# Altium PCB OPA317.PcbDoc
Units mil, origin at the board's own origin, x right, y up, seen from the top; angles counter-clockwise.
Board outline 2110 x 1700 mil, 2 copper layers (Top Layer, Bottom Layer), stack 62 mil thick; 30 components, 25 nets, 78 pads, 25 vias.
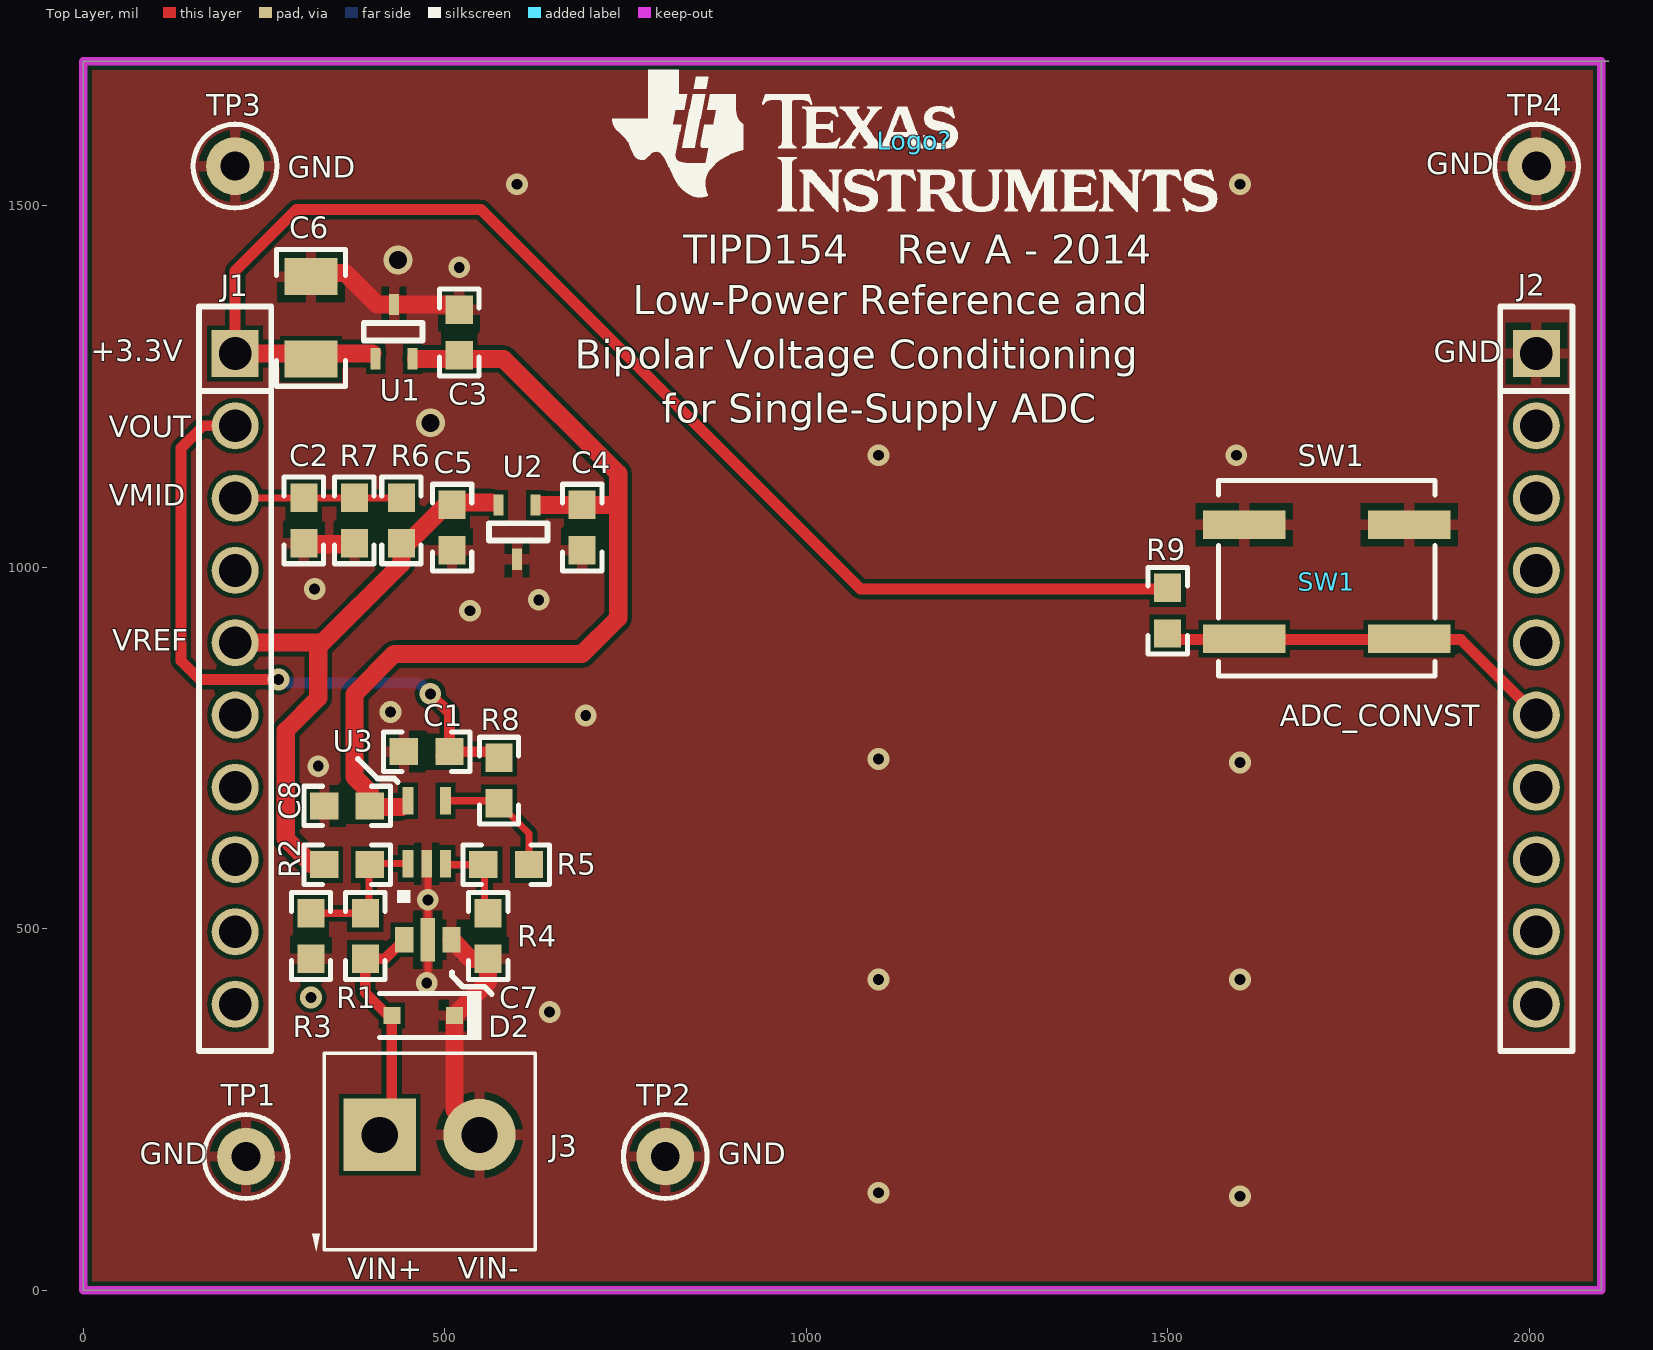
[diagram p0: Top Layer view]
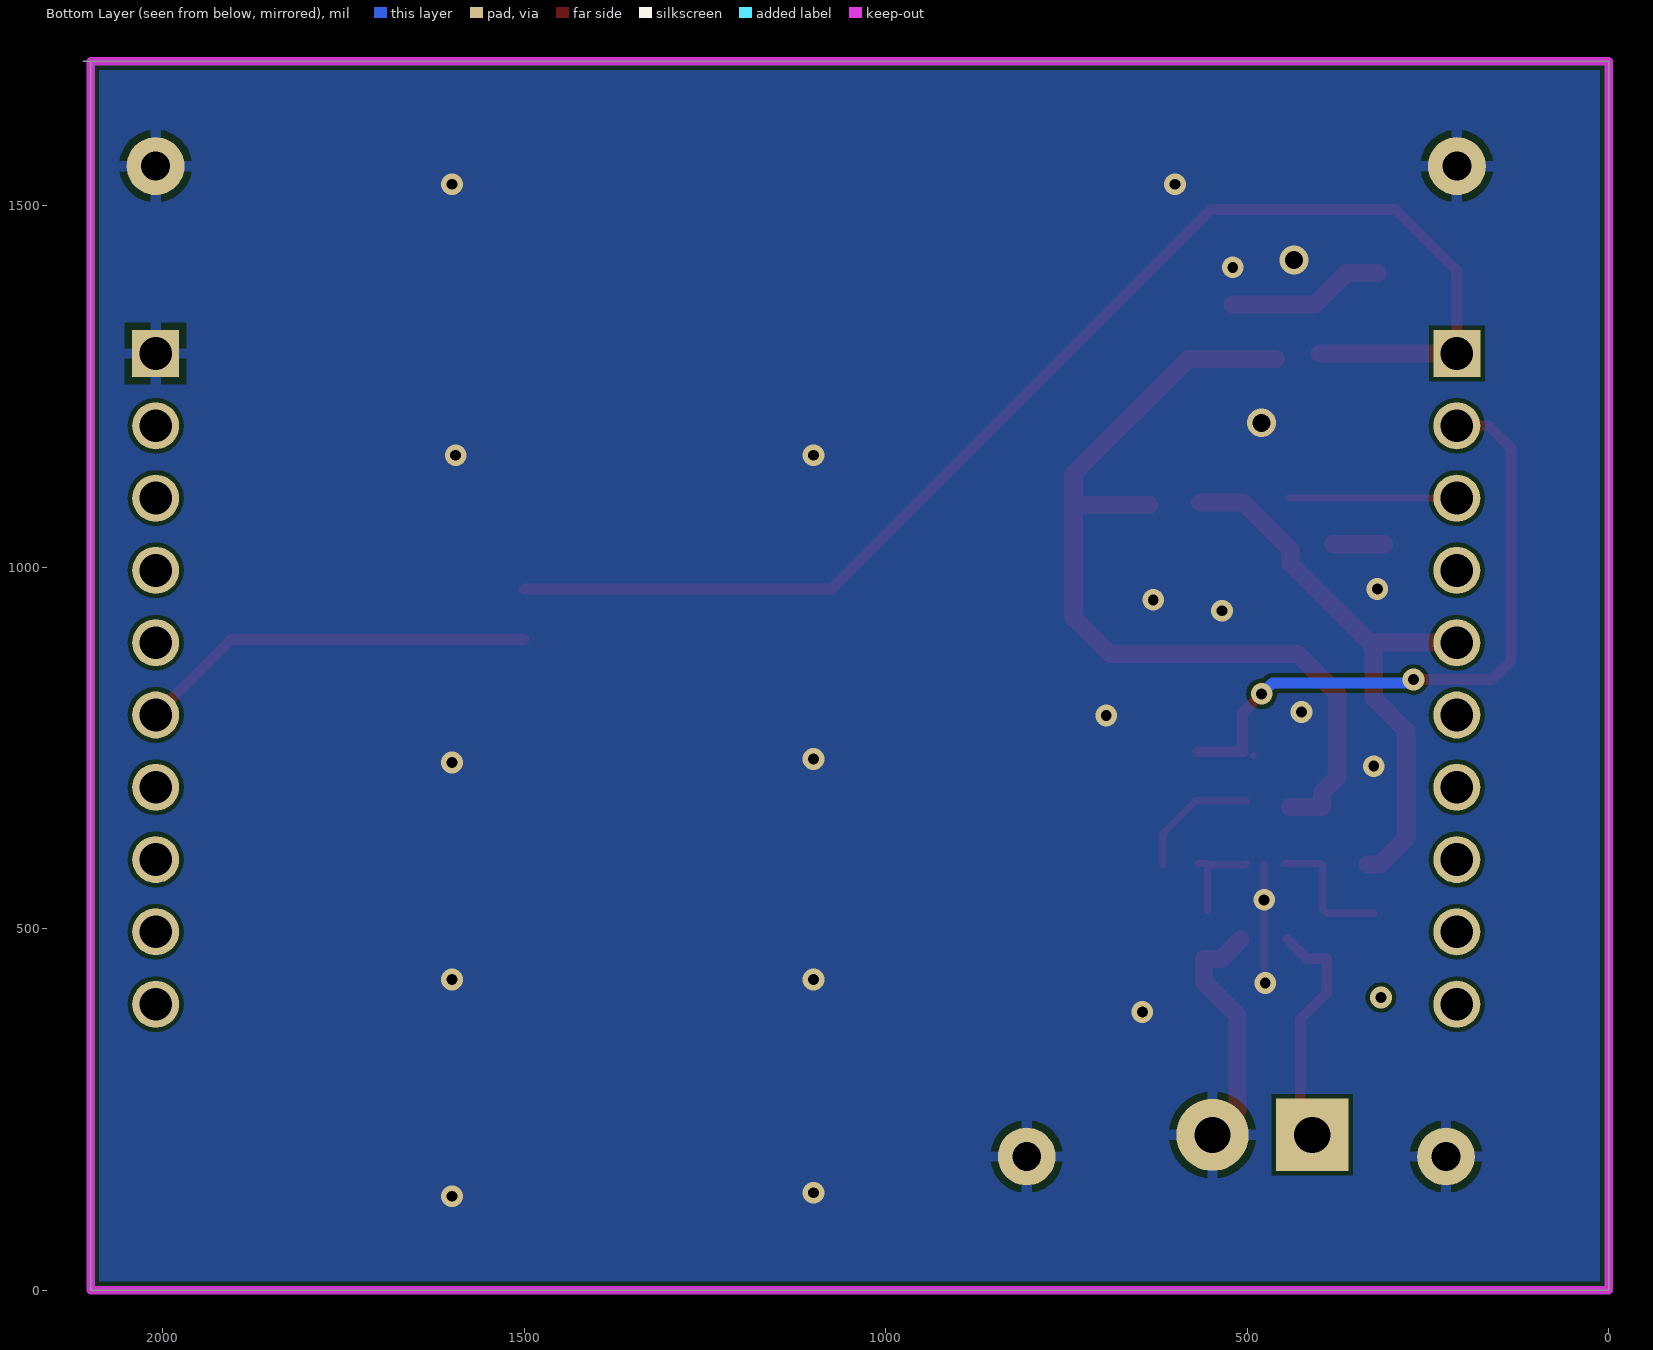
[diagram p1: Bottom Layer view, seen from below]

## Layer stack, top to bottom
Top Layer: signal copper 1.4
Dielectric: core 59.2, FR-4, Dk 4.8
Bottom Layer: signal copper 1.4

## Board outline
2110,1700 0,1700 0,0 2100,0 2100,1700

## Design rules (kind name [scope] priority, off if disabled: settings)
AcuteAngle [All] p1: minimum=4.50000000000000E+0001 checktracksonly=FALSE
AssemblyTestPointUsage [All] p1: valid=2
Clearance [All] p1: gap=6
DiffPairsRouting [All] p1: maxlimit=10 minlimit=10 mostfreqgap=10 maxuncoupledlength=1000
FanoutControl Fanout_LCC [IsLCC] p1: bgadir=Out bgaviamode=Centered fanoutstyle=Auto fanoutdirection=Alternating viagrid=1 // Fanout_LCC (Default Rule)
FanoutControl Fanout_BGA [IsBGA] p2: bgadir=Out bgaviamode=Centered fanoutstyle=Auto fanoutdirection=Alternating viagrid=1 // Fanout_BGA (Default Rule)
FanoutControl Fanout_Default [All] p4: bgadir=Out bgaviamode=Centered fanoutstyle=Auto fanoutdirection=Alternating viagrid=1 // Fanout_Default (Default Rule)
FanoutControl Fanout_Small [(CompPinCount < 5)] p5: bgadir=Out bgaviamode=Centered fanoutstyle=Auto fanoutdirection=OutThenIn viagrid=1 // Fanout_Small (Default Rule)
HoleToHoleClearance [All] p1: gap=0 allowstackedmicrovias=TRUE
MinimumSolderMaskSliver [All] p1: minsoldermaskwidth=0
PolygonConnect PolygonConnect_1 [(InComponentClass('All Components'))] p1: connectstyle=Relief reliefconductorwidth=15 reliefentries=4 polygonreliefangle="90 Angle" airgapwidth=10
PolygonConnect [All] p2: connectstyle=Direct reliefconductorwidth=20 reliefentries=4 polygonreliefangle="90 Angle" airgapwidth=10
RoutingVias [All] p1: holewidth=15 width=30 viastyle="Through Hole" minholewidth=15 minwidth=30 maxholewidth=28 maxwidth=50
SilkToSilkClearance [All] p1 off: silktosilkclearance=10
SilkscreenOverComponentPads [All] p1 off: minsilkscreentomaskgap=10
SolderMaskExpansion [All] p1: expansion=4
Width [All] p1: maxlimit=25 minlimit=10 preferedwidth=10
18 further rules are at their usual default settings.

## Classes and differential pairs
component class Logo: Logo?

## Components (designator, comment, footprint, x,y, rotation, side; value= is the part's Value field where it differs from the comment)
C1 "GRM188R71C154KA01D" 0603 475,745 r180 top
C2 "GRM188R60J476M" 0603 305,1065 r270 top
C3 "C1608X7R1C105K" 0603 520,1325 r90 top
C4 "C1608X7R1C105K" 0603 690,1055 r270 top
C5 "C1608X7R1C105K" 0603 510,1055 r270 top
C6 "C3216X7R1C106M" 1206 315,1345 r90 top
C7 "1000pF X2Y" X2Y_0603 476.59,485 r180 top
C8 "GRM188R71H104KA93D" 0603 365,670 r180 top
D2 "CDSOD323-T15SC" sod-323 470,380 r180 top
J1 "SSW-110-23-F-S" CONN_SSW-110-23-F-S 209.99,1295.82 r90 top
J2 "SSW-110-23-F-S" CONN_SSW-110-23-F-S 2009.99,1295.82 r90 top
J3 "ED555/2DS" TERM_BLK_ED555-2DS 410,215 r0 top
Logo? "Texas Instruments" TI_Stacked_Overlay_Small 1150,1590 r0 top
R1 "RG1608P-104-B-T5" 0603 390,490 r90 top
R2 "RG1608P-203-B-T5" 0603 365,588.7 r180 top
R3 "RG1608P-203-B-T5" 0603 315,490 r90 top
R4 "RG1608P-104-B-T5" 0603 560,490 r90 top
R5 "RG1608P-103-B-T5" 0603 585,588.7 r0 top
R6 "RG1608P-473-B-T5" 0603 440,1065 r270 top
R7 "RG1608P-473-B-T5" 0603 375,1065 r90 top
R8 "RT0603BRD071KL" 0603 575,705 r90 top
R9 "RG1608P-104-B-T5" 0603 1500,940 r90 top
SW1 "KSC222J LFS" "KSC222J LFS" 1720,980 r180 top
TP1 "5001" Keystone5001 225,185 r90 top
TP2 "5001" Keystone5001 805,185 r90 top
TP3 "5001" Keystone5001 210,1555 r90 top
TP4 "5001" Keystone5001 2010,1555 r90 top
U1 "REF3330AIDCKT" SC70 680,1525 r0 top
U2 "REF3312AIDCKR" SC70 350,850 r180 top
U3 "OPA317IDCKR" SC-70-5 475,633.7 r0 top

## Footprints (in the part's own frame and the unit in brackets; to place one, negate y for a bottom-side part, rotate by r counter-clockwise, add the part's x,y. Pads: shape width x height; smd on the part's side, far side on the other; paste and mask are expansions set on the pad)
0603 [mm] "0603 from SM-752 data"
  rect 1x0.95 smd: 1(-0.8,0) 2(0.8,0)
  silkscreen extent -1.52,-0.69 1.52,0.69, body extent -0.87,-0.47 0.87,0.47, height 0.85
1206 [mm] "1206 from SM-752 data"
  rect 1.3x1.85 smd: 1(-1.45,0) 2(1.45,0)
  silkscreen extent -2.4,-1.21 2.4,1.21, body extent -1.7,-0.9 1.7,0.9, height 1.35
CONN_SSW-110-23-F-S [mm] "SAMTEC"
  rect 1.65x1.65 hole 1.15: 1(0,0)
  round 1.65 hole 1.15: 2(-2.54,0) 3(-5.08,0) 4(-7.62,0) 5(-10.16,0) 6(-12.7,0) 7(-15.24,0) 8(-17.78,0) 9(-20.32,0) 10(-22.86,0)
  silkscreen extent -24.51,-1.27 1.65,1.27, body extent -24.43,-1.27 1.57,1.27, height 8.59
Keystone5001 [mil] "For Keystone 500x miniature loop terminals"
  round 80 hole 40: 1(0,0)
  silkscreen extent -58,-58 58,58, body extent -49,-49 49,49, height 182
"KSC222J LFS" [mm]
  rect 2.9x1 smd mask+0: 1(-2.9,2) 2(-2.9,-2) 3(2.9,-2) 4(2.9,2)
  silkscreen extent -3.81,-3.56 3.81,3.3, body extent -3.3,-3.05 3.3,3.05, height 3.51
SC70 [mm]
  rect 0.35x0.75 smd: 1(-7,-6) 2(-5.7,-6) 3(-6.35,-4.1)
  silkscreen extent -7.42,-5.36 -5.36,-4.75
SC-70-5 [mil]
  rect 15x38 smd: 1(-25.9,-43.4) 2(0.1,-43.4) 3(26.1,-43.4) 4(26.1,43.6) 5(-25.9,43.6)
  silkscreen extent -41,-97 -23,-80
sod-323 [mm] "NXP recommended land pattern"
  rect 0.6x0.6 smd paste-0.05: 1(-1.1,0) 2(1.1,0)
  silkscreen extent -2.06,-0.86 1.53,0.86, body extent -1.3,-0.67 1.3,0.68, height 1.1
TERM_BLK_ED555-2DS [mil]
  rect 100x100 hole 50: 1(0,0)
  round 100 hole 50: 2(138,0)
  silkscreen extent -93,-161 215,113, body extent -69,-150 207,106, height 323
TI_Stacked_Overlay_Small [mil]
  silkscreen extent -418,-98 418,98
X2Y_0603 [mm] "JOHANSON DIELECTRICS"
  rect 0.64x0.89 smd: 1(-0.83,0) 2(0.83,0)
  rect 0.51x1.52 smd: 3(0,0)
  body extent -0.88,-0.51 0.88,0.51, height 0.66

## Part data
C1: "CAP, CERM, 0.15uF, 16V, +/-10%, X7R, 0603"
C2: "CAP, CERM, 47uF, 6.3V, +/-20%, X5R, 0603"
C3 C4 C5: "CAP, CERM, 1uF, 16V, +/-10%, X7R, 0603"
C6: "CAP, CERM, 10uF, 16V, +/-20%, X7R, 1206"
C7: library part "X2Y Capacitor", "CAP CER 1000PF 50V 20% X7R 0603"
C8: "CAP, CERM, 0.1uF, 50V, +/-10%, X7R, 0603"
D2: library part SMAJ15CA, "DIODE TVS ARRAY 15V SOD323"
J1 J2: "Connector, Receptacle, 100mil, 10x1, Gold plated, TH"
J3: "Terminal Block, 6A, 3.5mm Pitch, 2-Pos, TH"
Logo?: library part TI_Logo, "Texas Instrument Corporate Signature"
R1 R4 R9: "RES, 100k ohm, 0.1%, 0.1W, 0603"
R2 R3: "RES, 20.0k ohm, 0.1%, 0.1W, 0603"
R5: "RES, 10.0k ohm, 0.1%, 0.1W, 0603"
R6 R7: "RES, 47.0k ohm, 0.1%, 0.1W, 0603"
R8: "RES, 1.00k ohm, 0.1%, 0.1W, 0603"
SW1: "SWITCH TACTILE SPST-NO 0.05A 32V"
TP1 TP2 TP3 TP4: "Test Point, Miniature, Black, TH"
U1 U2: library part REF33XXAIDBZ, "IC, 30 ppm/°C, 3.9 µA  xx-Voltage Reference"
U3: library part OPA349SA

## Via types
v1: diameter 30, hole 15, Top Layer to Bottom Layer, 23 vias
v2: diameter 40, hole 25, Top Layer to Bottom Layer, 2 vias

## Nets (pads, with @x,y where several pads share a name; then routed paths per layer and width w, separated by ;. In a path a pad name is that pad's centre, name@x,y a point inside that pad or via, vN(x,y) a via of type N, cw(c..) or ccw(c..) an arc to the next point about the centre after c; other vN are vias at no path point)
+3.3V: C6.1 J1.1 R9.2 U1.1 | length 1834.4
  Top Layer w15: J1.1@210,1308.32 210,1410 295,1495 550,1495 1075,970 R9.2@1500,970
  Top Layer w25: J1.1 U1.1@400,1295.82
+3V: C3.1 C4.1 C8.1 U1.2 U2.1 U3.5 | length 1265.6
  Top Layer w25: C8.1@396.5,668.7 440.5,668.7 ; C8.1 396.5,688.5 375,710 375,825 430,880 690,880 740,930 740,1130 581.5,1288.5 U1.2@460,1288.5 ; 635,1086.5 738.5,1086.5
GND: C1.2 C2.2 C3.2 C4.2 C5.2 C6.2 C7.1 C7.3 C8.2 D2.1 J2.1 J3.2 R3.1 R4.1 R7.1 SW1.2 SW1.3 TP1.1 TP2.1 TP3.1 TP4.1 U1.3 U2.3 U3.2 | length 792.2
  Top Layer w10: v1@476.59,425 U3.2@476.59,590.3
  Top Layer w25: C2.2@310.82,1032.01 R7.1@380.82,1032.01 ; C6.2@320,1407.09 362.91,1407.09 406.42,1363.58 C3.2@520,1363.58 ; C7.1 535.77,458.5 R4.1 560,426.69 D2.1 513.31,249.69 J3.2
  other v1: 1600,130 1100,135 645,385 475,425 1100,430 1600,430 476.59,540 325,725 1600,730 1100,735 695,795 425,800 535,940 630,955 320,970 1100,1155 1595,1155 520,1415 600,1530 1600,1530
  other v2: 480,1200 435,1425
J1.4: J1.4
J1.6: J1.6
J1.7: J1.7
J1.8: J1.8
J1.9: J1.9
J1.10: J1.10
J2.2: J2.2
J2.3: J2.3
J2.4: J2.4
J2.5: J2.5
J2.7: J2.7
J2.8: J2.8
J2.9: J2.9
J2.10: J2.10
NetC7_2: C7.2 D2.2 J3.1 R1.1 | length 367.6
  Top Layer w15: J3.1@405,180 426.69,201.69 426.69,375 390,411.69 R1.1 417.42,458.5 C7.2
NetR1_2: R1.2 R2.1 R3.2 U3.1 | length 178
  Top Layer w10: R3.2@325,521.5 R1.2 ; R1.2@395,525.2 R2.1@395,587.2 ; R2.1@398.1,590.3 U3.1
NetR4_2: R4.2 R5.1 U3.3 | length 131.8
  Top Layer w10: U3.3 502.7,588.7 R5.1 555,587.2 R4.2@555,525.2 ; R5.1@553.5,590.3 R5.1@568.1,590.3
NetR5_2: R5.2 R8.1 U3.4 | length 177.5
  Top Layer w10: U3.4 571.2,677.3 R8.1 616.5,632.01 R5.2
"START AD": J2.6 R9.1 SW1.1 SW1.4 | length 553.1
  Top Layer w15: R9.1@1500,900 1905.82,900 J2.6
VMID: C2.1 J1.3 R6.1 R7.2 | length 232.7
  Top Layer w10: J1.3 R6.1@442.74,1095.82
VOUT: C1.1 J1.2 R8.2 | length 898.6
  Top Layer w15: J1.2 165.82,1195.82 135,1165 135,870.85 161.03,844.82 v1(270,844.82) ; v1(480,825) 506.5,798.5 C1.1 R8.2@568.22,745
  Bottom Layer w15: v1(270,844.82) 274.82,840 465,840 v1(480,825)
VREF: C5.1 J1.5 R2.2 R6.2 U2.2 | length 799.9
  Top Layer w25: J1.5 325,895.82 325,819.01 280,774.01 280,625 316.3,588.7 R2.2 ; 330.41,895.41 440,1005 440,1025 505,1090 565,1090
copper on no net:
  other v1: 315,405

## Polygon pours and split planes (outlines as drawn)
GND on Bottom Layer "Top Layer-No Net" (solid, remove dead copper, pour order 5): 0,1700 2120.16,1700 2120.16,-10.16 0,-10.16
GND on Top Layer "Top Layer-No Net" (solid, remove dead copper, pour order 8): 0,1710 2110.16,1710 2110.16,-0.16 0,-0.16

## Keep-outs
Keep-Out Layer:
  lines w11.81: 0,0 2100,0 2100,1700 0,1700 0,0

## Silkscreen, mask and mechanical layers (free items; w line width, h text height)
Top Overlay:
  lines w8: 380,735 407,708 430,708 435,703 ; 510,440 510,435 525,420 555,420 565,410
  text "GND" at 1858,1544 h30
  text "GND" at 283,1539 h30
  text "TIPD154" at 830,1420 h40
  text "Rev A - 2014" at 1125,1420 h40
  text "Low-Power Reference and" at 760,1350 h40
  text "+3.3V" at 10,1285 h30
  text "GND" at 1868,1284 h30
  text "Bipolar Voltage Conditioning" at 680,1275 h40
  text "for Single-Supply ADC" at 800,1200 h40
  text "VOUT" at 35,1180 h30
  text "SW1" at 1680,1140 h30
  text "VMID" at 35,1085 h30
  text "VREF" at 40,885 h30
  text "ADC_CONVST" at 1655,780 h30
  text "GND" at 78,174 h30
  text "GND" at 878,174 h30
  text "VIN-" at 518,16 h30
  text "VIN+" at 365,15 h30
M1 Board Outline:
  lines w8: 0,0 0,1700 2100,1700 2100,0 0,0

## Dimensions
-50,1700 to -55,0 on M2 Board Dimensions
0,-70 to 2100,0 on M2 Board Dimensions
